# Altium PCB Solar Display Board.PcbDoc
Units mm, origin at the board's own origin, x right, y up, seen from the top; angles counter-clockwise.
Board outline 45 x 20 mm, 2 copper layers (Top Layer, Bottom Layer), stack 1.57 mm thick; 17 components, 18 nets, 42 pads, 3 vias.
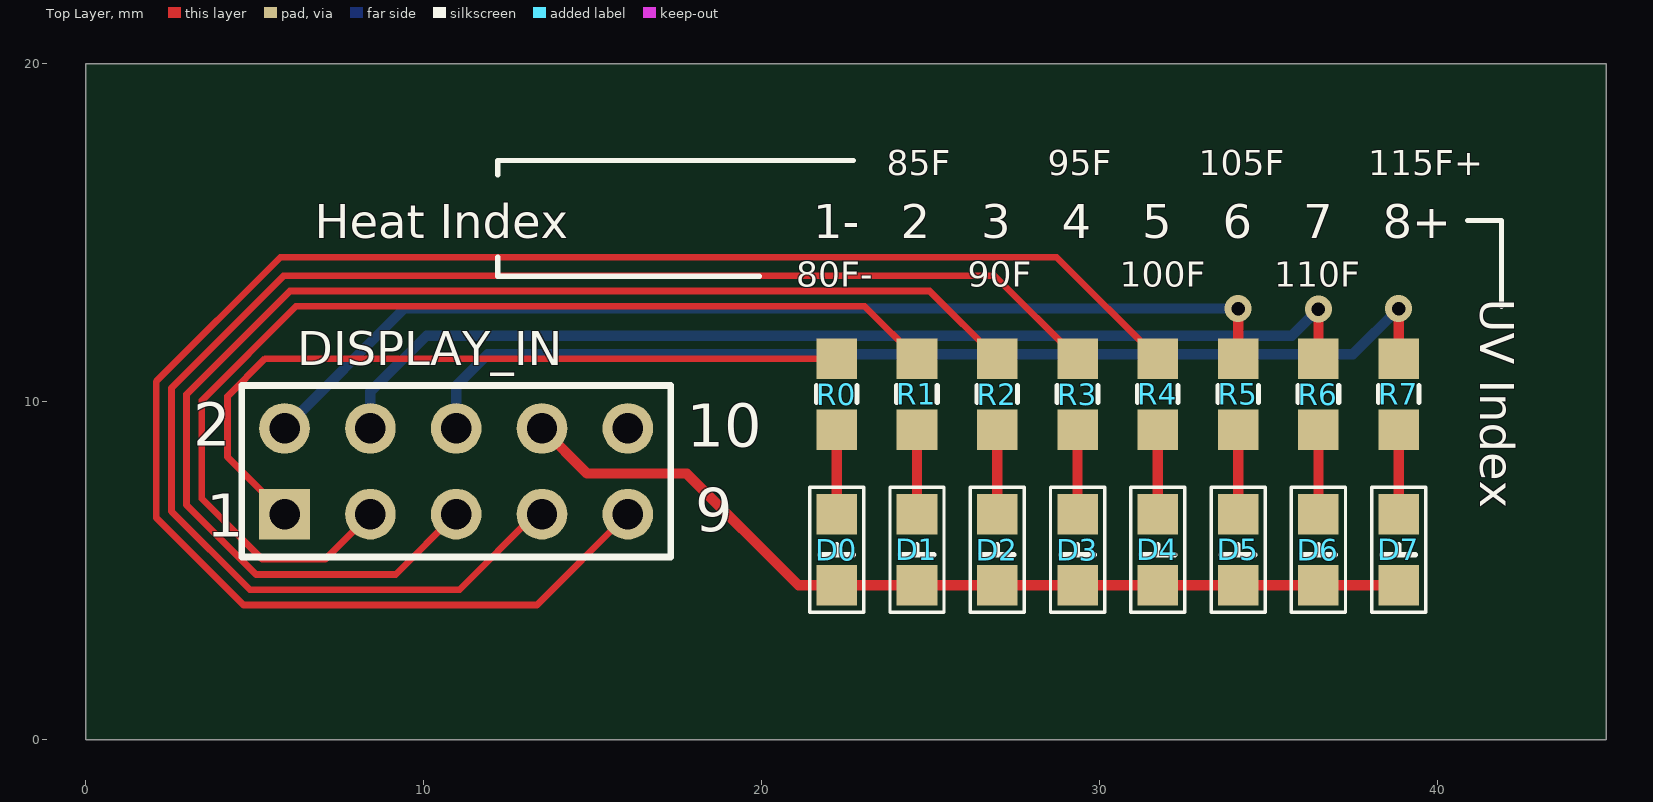
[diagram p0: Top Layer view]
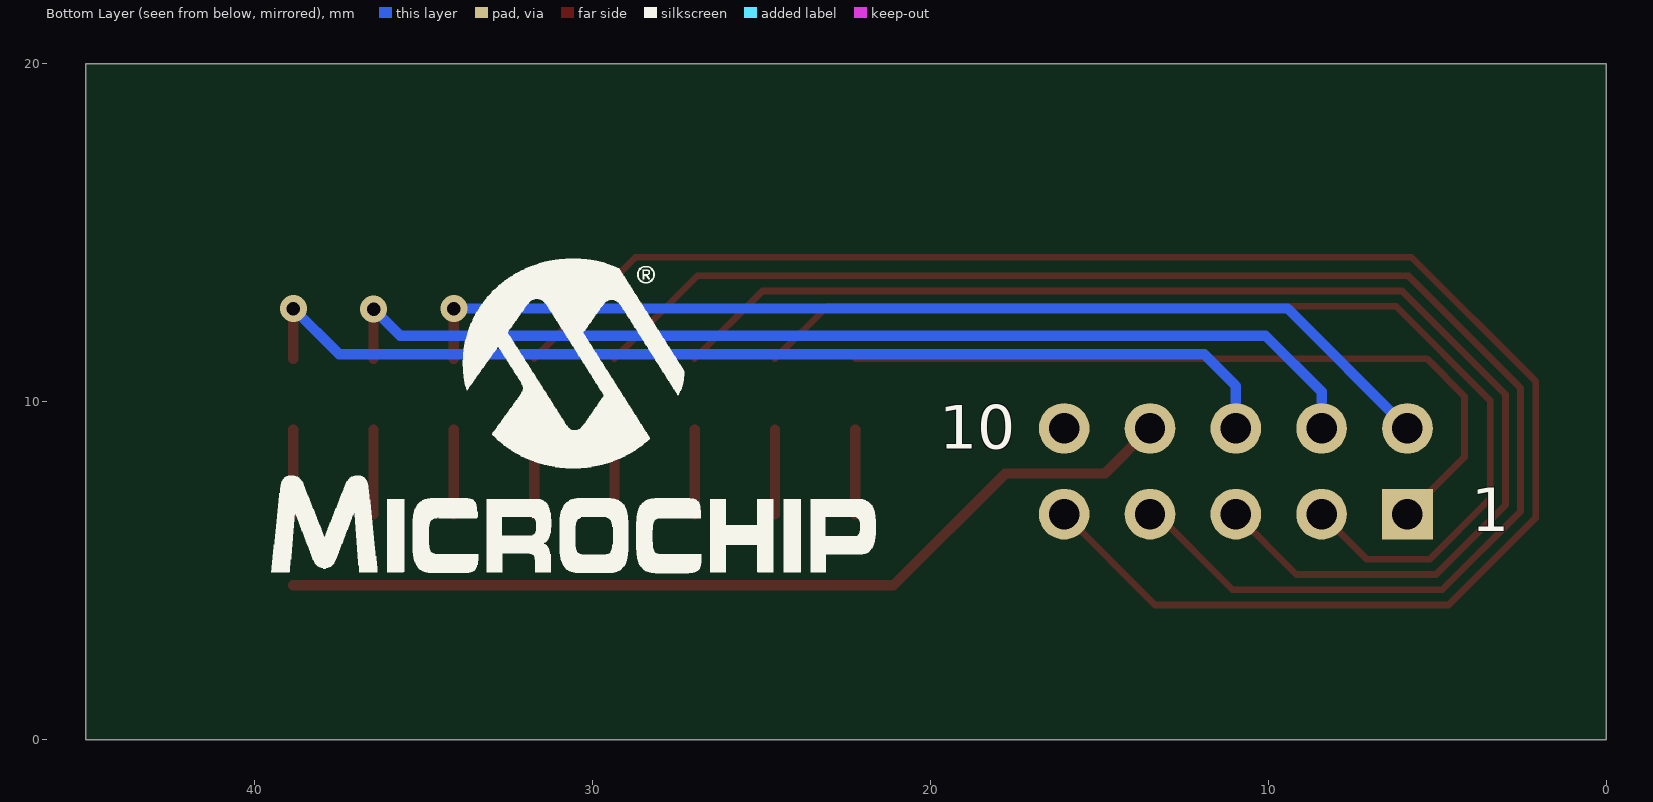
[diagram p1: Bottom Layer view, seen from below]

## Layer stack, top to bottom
Top Solder: solder mask 0.01, Solder Resist, Dk 3.5
Top Layer: signal copper 0.035
Dielectric1: core 1.5, FR-4, Dk 4.8
Bottom Layer: signal copper 0.035
Bottom Solder: solder mask 0.01, Solder Resist, Dk 3.5

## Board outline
0,0 0,20 45,20 45,0

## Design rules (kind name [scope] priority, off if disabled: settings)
AcuteAngle [All] p1: minimum=9.00000000000000E+0001 checktracksonly=TRUE
BoardOutlineClearance BoardOutlineClearance_Overlay [OnLayer('Top Overlay','Bottom Overlay')] p1: gap=0.2 ignorepadtopadclearanceinfootprint=FALSE
BoardOutlineClearance [All] p2: gap=0.5 ignorepadtopadclearanceinfootprint=FALSE
Clearance "Net to Polygon 0.5mm" [InNet('your net here') vs (IsRegion)] p1: gap=0.5 ignorepadtopadclearanceinfootprint=FALSE
Clearance "Poly 0.3mm" [(IsRegion)] p2: gap=0.3 ignorepadtopadclearanceinfootprint=FALSE
Clearance [All] p3: gap=0.25 ignorepadtopadclearanceinfootprint=TRUE
ComponentClearance ComponentClearance_ignore [HasFootprint('NET_TIE_0.5mm')] p1: gap=0 collisioncheckmode=3 verticalgap=0 showdistances=FALSE
ComponentClearance [All] p2: gap=0.2 collisioncheckmode=3 verticalgap=0.2 showdistances=FALSE
DiffPairsRouting [All] p1: maxlimit=0.25 minlimit=0.25 mostfreqgap=0.25 toplayer_minwidth=0.25 toplayer_maxwidth=0.25 toplayer_prefwidth=0.25 bottomlayer_minwidth=0.25 bottomlayer_maxwidth=0.25 bottomlayer_prefwidth=0.25 maxuncoupledlength=12.7
FabricationTestPointUsage TestPointUsage [All] p1: valid=0 allowmultiple=FALSE
FabricationTestpoint Testpoint [All] p1: side=3 testpointundercomponent=TRUE minsize=1.016 maxsize=2.54 preferedsize=1.524 minholesize=0 maxholesize=1.016 preferedholesize=0.813 testpointgrid=0.025 allowsidetop=TRUE allowsidebottom=TRUE usegrid=TRUE gridtolerance=0
HoleSize [All] p1: absolutevalues=TRUE maxlimit=6 minlimit=0.25 maxpercent=80.000 minpercent=20.000
HoleToHoleClearance [All] p1: gap=0.3 allowstackedmicrovias=FALSE
MinimumAnnularRing [All] p1: minimumring=0.15
MinimumSolderMaskSliver [All] p1: minsoldermaskwidth=0.15
PasteMaskExpansion PasteMaskExpansion_DNP [IsPad AND HasCompParameterValue('Populated','DNP')] p1: expansion=-5
PasteMaskExpansion [All] p2: expansion=0
PlaneClearance PlaneClearance_pads [IsPad] p1: clearance=0.3
PlaneClearance PlaneClearance_drill [IsObjectKind('Hole')] p2: clearance=0.4
PlaneConnect PlaneConnect_full [IsVia] p1: planeconnectstyle=Direct reliefexpansion=0.5 reliefentries=4 reliefconductorwidth=0.3 reliefairgap=0.3
PlaneConnect [All] p2: planeconnectstyle=Relief reliefexpansion=0.3 reliefentries=4 reliefconductorwidth=0.25 reliefairgap=0.25
PolygonConnect PolygonConnect_0.7 [IsNamedPolygon('0.7mm') vs (InPadClass('All Pads'))] p1: connectstyle=Relief reliefconductorwidth=0.7 reliefentries=4 polygonreliefangle="90 Angle" airgapwidth=0.25
PolygonConnect PolygonConnect_0.5 [IsNamedPolygon('0.5mm') vs (InPadClass('All Pads'))] p2: connectstyle=Relief reliefconductorwidth=0.5 reliefentries=4 polygonreliefangle="90 Angle" airgapwidth=0.25
PolygonConnect PolygonConnect_full [All vs IsVia or IsNamedPolygon('full')] p3: connectstyle=Direct reliefconductorwidth=0 reliefentries=4 polygonreliefangle="90 Angle" airgapwidth=0.254
PolygonConnect [All] p4: connectstyle=Relief reliefconductorwidth=0.3 reliefentries=4 polygonreliefangle="90 Angle" airgapwidth=0.25
RoutingCorners [All] p1: cornerstyle=45-Degree minsetback=2.5 maxsetback=2.5
RoutingVias [All] p1: holewidth=0.4 width=0.8 viastyle="Through Hole" minholewidth=0.3 minwidth=0.7 maxholewidth=1.6 maxwidth=2.5
SMDToCorner [All] p1: distance=39370
ShortCircuit [IsNet] p1: allowed=FALSE
SilkToSilkClearance [All] p1: silktosilkclearance=0.15
SilkToSolderMaskClearance SilkscreenOverComponentPads [IsPad] p1: minsilkscreentomaskgap=0.2 clearancetoexposedcopper=TRUE
SolderMaskExpansion SolderMaskExpansion_Component_Via [IsComponentVia] p1: expansion=0.075 istentingtop=FALSE soldermaskfromhole=TRUE
SolderMaskExpansion [All] p2: expansion=0.1 istentingtop=FALSE
UnRoutedNet [All] p1: checkbadconnections=TRUE
ViasUnderSMD [All] p1: allowed=FALSE
Width [All] p1: maxlimit=7 minlimit=0.2 preferedwidth=0.25
15 further rules are at their usual default settings.

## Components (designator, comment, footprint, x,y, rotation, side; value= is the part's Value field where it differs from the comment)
D0 "LED" "0805 for LED" 22.225,4.572 r90 top
D1 "LED" "0805 for LED" 24.602,4.572 r90 top
D2 "LED" "0805 for LED" 26.978,4.572 r90 top
D3 "LED" "0805 for LED" 29.355,4.572 r90 top
D4 "LED" "0805 for LED" 31.732,4.572 r90 top
D5 "LED" "0805 for LED" 34.109,4.572 r90 top
D6 "LED" "0805 for LED" 36.485,4.572 r90 top
D7 "LED" "0805 for LED" 38.862,4.572 r90 top
DISPLAY_IN "Header 5X2" HDR2X5 5.88,6.672 r0 top
R0 "Resistor" 0805 22.225,11.275 r270 top value=330
R1 "Resistor" 0805 24.602,11.275 r270 top value=330
R2 "Resistor" 0805 26.978,11.275 r270 top value=330
R3 "Resistor" 0805 29.355,11.275 r270 top value=330
R4 "Resistor" 0805 31.732,11.275 r270 top value=330
R5 "Resistor" 0805 34.109,11.275 r270 top value=330
R6 "Resistor" 0805 36.485,11.275 r270 top value=330
R7 "Resistor" 0805 38.862,11.275 r270 top value=330

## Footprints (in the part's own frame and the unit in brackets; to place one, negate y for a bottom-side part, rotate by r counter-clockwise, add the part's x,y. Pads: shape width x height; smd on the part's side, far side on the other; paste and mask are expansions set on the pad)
0805 [mm] "Non-Polarized"
  rect 1.2x1.2 smd: 1(0,0) 2(2.1,0)
  silkscreen extent 0.8,-0.6 1.3,0.6
"0805 for LED" [mm] "Polarized 0805 Package"
  rect 1.2x1.2 smd: A(0,0) K(2.1,0)
  silkscreen extent -0.8,-0.8 2.9,0.8
HDR2X5 [mm] "Connector; Header; 5x2 Position"
  rect 1.5x1.5 hole 0.9: 1(0,0)
  round 1.5 hole 0.9: 2(0,2.54) 3(2.54,0) 4(2.54,2.54) 5(5.08,0) 6(5.08,2.54) 7(7.62,0) 8(7.62,2.54) 9(10.16,0) 10(10.16,2.54)
  silkscreen extent -1.27,-1.27 11.43,3.81

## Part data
D0 D1 D2: LED Color=Green
D3 D4 D5: LED Color=Yellow
D6 D7: LED Color=Red
DISPLAY_IN: "Header, 5-Pin, Dual row"

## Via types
v1: diameter 0.8, hole 0.4, Top Layer to Bottom Layer, 3 vias

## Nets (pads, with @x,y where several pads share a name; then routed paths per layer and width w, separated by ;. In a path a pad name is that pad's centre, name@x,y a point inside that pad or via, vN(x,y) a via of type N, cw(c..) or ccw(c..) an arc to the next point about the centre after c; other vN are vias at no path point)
GND: DISPLAY_IN.10
IO0: DISPLAY_IN.1 R0.1 | length 22.7
  Top Layer w0.2: DISPLAY_IN.1 4.191,8.361 4.191,10.16 5.306,11.275 R0.1
IO1: DISPLAY_IN.3 R1.1 | length 32.2
  Top Layer w0.2: DISPLAY_IN.3 7.082,5.334 5.223,5.334 3.429,7.128 3.429,10.034 6.222,12.827 23.049,12.827 R1.1
IO2: DISPLAY_IN.5 R2.1 | length 38.9
  Top Layer w0.2: DISPLAY_IN.5 9.172,4.884 5.037,4.884 2.979,6.942 2.979,10.221 6.035,13.277 24.976,13.277 R2.1
IO3: DISPLAY_IN.7 R3.1 | length 45.7
  Top Layer w0.2: DISPLAY_IN.7 13.296,6.672 11.058,4.434 4.85,4.434 2.529,6.755 2.529,10.407 5.849,13.727 26.903,13.727 R3.1
IO4: DISPLAY_IN.9 R4.1 | length 52.6
  Top Layer w0.2: DISPLAY_IN.9 13.352,3.984 4.664,3.984 2.079,6.569 2.079,10.594 5.763,14.277 28.729,14.277 R4.1
IO5: DISPLAY_IN.2 R5.1 | length 31.2
  Top Layer w0.305: R5.1 v1(34.109,12.76)
  Bottom Layer w0.305: DISPLAY_IN.2 9.428,12.76 v1(34.109,12.76)
IO6: DISPLAY_IN.4 R6.1 | length 31.6
  Top Layer w0.305: R6.1 v1(36.485,12.742)
  Bottom Layer w0.305: DISPLAY_IN.4 8.42,10.297 10.081,11.957 35.7,11.957 v1(36.485,12.742)
IO7: DISPLAY_IN.6 R7.1 | length 31.6
  Top Layer w0.305: R7.1 v1(38.862,12.76)
  Bottom Layer w0.305: DISPLAY_IN.6 10.96,10.468 11.894,11.403 37.505,11.403 v1(38.862,12.76)
"LED Anode": D0.A D1.A D2.A D3.A D4.A D5.A D6.A D7.A DISPLAY_IN.8 | length 27.3
  Top Layer w0.305: DISPLAY_IN.8 14.838,7.874 17.791,7.874 21.093,4.572 D0.A D1.A D2.A D3.A D4.A D5.A D6.A D7.A
NetD0_K: D0.K R0.2 | length 2.5
  Top Layer w0.305: D0.K R0.2
NetD1_K: D1.K R1.2 | length 2.5
  Top Layer w0.305: D1.K R1.2
NetD2_K: D2.K R2.2 | length 2.5
  Top Layer w0.305: D2.K R2.2
NetD3_K: D3.K R3.2 | length 2.5
  Top Layer w0.305: D3.K R3.2
NetD4_K: D4.K R4.2 | length 2.5
  Top Layer w0.305: D4.K R4.2
NetD5_K: D5.K R5.2 | length 2.5
  Top Layer w0.305: D5.K R5.2
NetD6_K: D6.K R6.2 | length 2.5
  Top Layer w0.305: D6.K R6.2
NetD7_K: D7.K R7.2 | length 2.5
  Top Layer w0.305: D7.K R7.2

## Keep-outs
Keep-Out Layer:
  text "'.Layer_Name'" at 300.5,-158.75 h1.5

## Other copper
Top Layer:
  text "'.ProjectRevisionART'" at 335.678,-158.572 h1.5
  text "'.Layer_Name'" at 300.5,-158.75 h1.5
Bottom Layer:
  text "04-'.ProjectPCBNumber'-R'.ProjectRevisionART'" at 242,-108.5 h1.2
  text ".ProjectRevisionART" at 335.678,-158.572 h1.5
  text ".ProjectRevisionART" at 335.678,-158.572 h1.5
  text "'.ProjectRevisionART'" at 335.678,-158.572 h1.5
  text "'.Layer_Name'" at 300.5,-158.75 h1.5

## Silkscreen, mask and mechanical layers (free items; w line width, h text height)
Top Overlay:
  region: 289.8,-122.1 289.8,-120.1 291.8,-121.1
  lines w0.152: 12.192,14.277 12.192,13.716 19.939,13.716 ; 12.192,16.71 12.192,17.145 22.725,17.145 ; 40.894,15.367 41.91,15.367 41.91,13.97 41.91,12.827
  text "85F" at 23.7,16.71 h0.75
  text "95F" at 28.467,16.71 h0.75
  text "105F" at 32.942,16.71 h0.75
  text "115F+" at 37.961,16.71 h0.75
  text "Heat Index" at 6.774,14.844 h1
  text "1-" at 21.536,14.844 h1
  text "2" at 24.127,14.844 h1
  text "3" at 26.509,14.844 h1
  text "4" at 28.891,14.844 h1
  text "5" at 31.273,14.844 h1
  text "6" at 33.654,14.844 h1
  text "7" at 36.036,14.844 h1
  text "8+" at 38.383,14.844 h1
  text "80F-" at 21.028,13.408 h0.75
  text "90F" at 26.108,13.408 h0.75
  text "100F" at 30.611,13.408 h0.75
  text "110F" at 35.175,13.408 h0.75
  text "UV Index" at 41.275,13.047 h1 r270
  text "C" at 251.245,-112.043 h8
  text "1" at 260.096,-112.649 h5
  text "'.ProjectPartNumber'" at 231.5,-113 h1.2
  text "" at 244.245,-113.346 h8
  text "5" at 278.5,-114.194 h8
  text "7" at 288.5,-114.194 h8
  text "0" at 298.5,-114.194 h8
  text "1" at 308.5,-114.194 h8
  text "6" at 268.5,-114.227 h8
  text "2" at 318.5,-114.227 h8
  text "3" at 328.5,-114.227 h8
  text "4" at 338.58,-114.227 h8
  text "ICD" at 284.4,-122 h1.52
  text "M" at 262,-128.5 h10
  text "" at 315,-128.959 h10
  text "" at 294,-128.984 h10
  text "" at 305,-128.984 h10
  text "" at 324,-128.984 h10
  text "" at 335,-128.984 h10
  text "" at 346,-129.159 h10
  text "*h" at 227.7,-130 h7
  text "" at 286,-132 h10
  text "dsPICDEM.net™" at 185.75,-138.75 h3
  text "mTouch®" at 208,-138.75 h3
  text "chipKIT™" at 222.25,-138.75 h3
  text "dsPICDEM™" at 185.5,-144.5 h3
  text "MPLAB®" at 208,-145 h3
  text "dsPIC®" at 222.25,-145 h3
  text "PICDEM.net™" at 185.5,-150.75 h3
  text "PICkit™" at 208.25,-151 h3
  text "PIC®" at 222.25,-151 h3
  text "PICDEM™" at 185.5,-157.25 h3
  text "PICtail™" at 208.25,-157.25 h3
  text "'.ProjectRevisionART'" at 335.678,-158.572 h1.5
  text "'.Layer_Name'" at 300.5,-158.75 h1.5
Bottom Overlay:
  drawing of 12 lines, arcs and shapes, not listed
  text "10" at 19.739,8.606 h1.3
  text "1" at 3.991,6.169 h1.3
  text "'.ProjectRevisionART'" at 335.678,-158.572 h1.5
  text "'.Layer_Name'" at 300.5,-158.75 h1.5
Top Paste:
  text "'.ProjectRevisionART'" at 335.678,-158.572 h1.5
  text "'.Layer_Name'" at 300.5,-158.75 h1.5
Bottom Paste:
  text "'.ProjectRevisionART'" at 335.678,-158.572 h1.5
  text "'.Layer_Name'" at 300.5,-158.75 h1.5
Top Solder:
  text "'.ProjectRevisionART'" at 335.678,-158.572 h1.5
  text "'.Layer_Name'" at 300.5,-158.75 h1.5
Bottom Solder:
  text "'.ProjectRevisionART'" at 335.678,-158.572 h1.5
  text "'.Layer_Name'" at 300.5,-158.75 h1.5
NOTES (M1):
  text "ASSEMBLY NOTES:" at 29.4,-109.1 h4
  text "1. ALL COMPONENTS SHALL BE RoHS COMPLIANT." at -4.7,-114.2 h3
  text "2. ALL UNUSED THROUGH HOLE COMPONENT LOCATIONS SHALL BE FREE OF SOLDER." at -4.7,-117.2 h3
  text "3. ALL COMPONENTS SHALL BE MOUNTED FLUSH TO THE BOARD, EXCEPT AS NOTED." at -4.7,-120.2 h3
  text "4. FINISHED BOARD SHALL BE FREE OF ALL RESIDUES." at -4.7,-123.2 h3
  text "5. ALL LEADS SHALL BE TRIMMED TO A MAXIMUM HEIGHT OF 2mm" at -4.7,-126.2 h3
  text "'.Layer_Name'" at 318.5,-158.75 h1.5
BOARD (M2):
  the board outline again, w0.1
  text "'.ProjectRevisionART'" at 335.678,-158.572 h1.5
  text "'.Layer_Name'" at 300.5,-158.75 h1.5
REF POINTS (M3):
  text "'.Layer_Name'" at 300.5,-158.75 h1.5
FAB (M4):
  drawing of 284 lines, arcs and shapes, not listed
  text "THIS PCB TO BE MANUFACTURED TO MEET ALL ACCEPTANCE LEVELS" at 236.989,51.662 h1.78
  text "OF A CLASS 2 PCB PER ANSI/IPC-A-600G." at 236.989,47.852 h1.78
  text "MATERIAL:" at 236.989,43.232 h1.78
  text "FR-4 or Equivalent" at 257.309,43.232 h1.78
  text "CONTROLLED IMPEDANCE" at 313.5,39 h1.78
  text "MULTILAYER" at 263.024,38.882 h1.78
  text "2" at 286.519,38.882 h1.78
  text "LAYERS" at 290.964,38.882 h1.78
  text "Cu WEIGHT EXTERNAL LAYERS" at 257.309,34.032 h1.78
  text "35um" at 309.379,34.032 h1.78
  text "FINISHED" at 318.904,34.032 h1.78
  text "Cu WEIGHT INTERNAL LAYERS" at 257.309,29.182 h1.78
  text "N/A" at 309.379,29.182 h1.78
  text "FINISHED" at 318.904,29.182 h1.78
  text "FINISHED OVERALL THICKNESS" at 257.309,24.332 h1.78
  text "1.6" at 310.649,24.332 h1.78
  text "mm" at 318.904,24.332 h1.78
  text "10" at 333.509,24.332 h1.78
  text "%" at 341.764,24.332 h1.78
  text "COPPER THIEVING ALLOWED" at 257.5,19.5 h1.78
  text "YES" at 314.5,19.5 h1.78
  text "NO" at 331.5,19.5 h1.78
  text "X" at 326.091,19 h2.6
  text "FINISH:" at 237,15 h1.78
  text "LEAD-FREE HOT AIR LEVELING" at 263,14.7 h1.78
  text "X" at 258.4,14 h2.6
  text "IMMERSION GOLD" at 263.024,9.162 h1.78
  text "IMMERSION TIN" at 263.024,3.662 h1.78
  text "SMOBC WITH SELECTIVE GOLD PLATING ON LANDS" at 263.024,-0.043 h1.78
  text "INDICATED. 1um GOLD OVER 5-10 um NICKEL" at 263.024,-3.853 h1.78
  text "SOLDERMASK" at 257.309,-9.188 h1.78
  text "DYNACHEM EPIC 200 LPI OR EQUIVALENT" at 278.899,-9.188 h1.78
  text "SOLDERMASK COLOR" at 257.309,-15.538 h1.78
  text "GREEN HIGH GLOSS" at 289.059,-15.538 h1.78
  text "SILKSCREEN COLOR" at 257.309,-21.888 h1.78
  text "WHITE" at 289.059,-21.888 h1.78
  text "Blind / Burried Vias" at 263.5,-28 h1.78
  text "DRILLING:" at 237.5,-28.25 h1.78
  text "Via Layer Pairs" at 258,-32.75 h1.78
  text "Top-Bottom" at 278.75,-32.75 h1.78
  text "ALL HOLES TO BE LOCATED BY THE COORDINATES FROM THE NC DRILL DATA PROVIDED." at 236.989,-38 h1.78
  text "05-'.ProjectPCBNumber'" at 269,-44.5 h1.78
  text "PCB REV" at 305,-44.5 h1.78
  text "USE ARTWORK SET NO." at 236.989,-44.588 h1.78
  text "'.ProjectRevisionART'" at 318.15,-44.75 h1.78
  text "ALL UL LOGO, MANUFACTURER'S ID, AND DATE CODES SHALL BE PLACED" at 236.989,-50.938 h1.78
  text "ON THE BOTTOM SIDE UNLESS OTHERWISE INDICATED." at 236.989,-54.748 h1.78
  text "ANY ALTERNATIVES TO THE ABOVE SPECIFICATIONS MUST FIRST BE APPROVED." at 236.5,-60 h1.78
  text "Layer" at 224.029,-66.675 h1.52
  text "Name" at 234.441,-66.675 h1.52
  text "Material" at 258.056,-66.675 h1.52
  text "Thickness" at 279.894,-66.675 h1.52
  text "Constant" at 296.4,-66.675 h1.52
  text "Gerber" at 310.875,-66.675 h1.52
  text "Board Layer Stack" at 322.81,-66.675 h1.52
  text "Top Overlay" at 234.441,-69.723 h1.52
  text "GTO" at 310.875,-69.723 h1.52
  text "Top Solder" at 234.441,-72.771 h1.52
  text "Solder Resist" at 258.056,-72.771 h1.52
  text "0.010mm" at 279.894,-72.771 h1.52
  text "3.5" at 296.4,-72.771 h1.52
  text "GTS" at 310.875,-72.771 h1.52
  text "1" at 224.029,-75.819 h1.52
  text "Top Layer" at 234.441,-75.819 h1.52
  text "0.035mm" at 279.894,-75.819 h1.52
  text "GTL" at 310.875,-75.819 h1.52
  text "Dielectric1" at 234.441,-78.867 h1.52
  text "FR-4" at 258.056,-78.867 h1.52
  text "1.500mm" at 279.894,-78.867 h1.52
  text "4.8" at 296.4,-78.867 h1.52
  text "2" at 224.029,-81.915 h1.52
  text "Bottom Layer" at 234.441,-81.915 h1.52
  text "0.035mm" at 279.894,-81.915 h1.52
  text "GBL" at 310.875,-81.915 h1.52
  text "Bottom Solder" at 234.441,-84.963 h1.52
  text "Solder Resist" at 258.056,-84.963 h1.52
  text "0.010mm" at 279.894,-84.963 h1.52
  text "3.5" at 296.4,-84.963 h1.52
  text "GBS" at 310.875,-84.963 h1.52
  text "Bottom Overlay" at 234.441,-88.011 h1.52
  text "GBO" at 310.875,-88.011 h1.52
  text "Total board thickness:" at 224.029,-91.059 h1.52
  text "1.590mm" at 279.894,-91.059 h1.52
  text "'.ProjectRevisionFAB'" at 335.678,-158.572 h1.5
  text "'.Layer_Name'" at 300.5,-158.75 h1.5
Case (M5):
  text "'.Layer_Name'" at 300.5,-158.75 h1.5
Cover (M6):
  text "'.Layer_Name'" at 300.5,-158.75 h1.5
Terminal Block (M7):
  text "'.Layer_Name'" at 300.5,-158.75 h1.5
Route Tool Path:
  text "'.Layer_Name'" at 300.5,-158.75 h1.5
V-Cut (M9):
  text "'.Layer_Name'" at 300.5,-158.75 h1.5
Bottom Assembly:
  text "'.VariantName'" at 50.07,-142.75 h0.9
  text "ASSEMBLY VARIANT:" at 64.32,-142.75 h0.9
  text "DOCUMENT NUMBER:" at 18.05,-151 h1.14
  text "02-'.ProjectPCBAssyNumber'-D" at 17.8,-154 h1.6
  text "'.ProjectRevisionASSY'" at 1.122,-158.572 h1.5
  text "'.Layer_Name'" at 36,-158.75 h1
Top Assembly:
  text "6. PLACE LABEL  ON THE LOCATION INDICATED." at -4.7,-129.2 h3
  text "7." at -4.7,-132.2 h3
  text "ASSEMBLY VARIANT:" at 272.5,-142.75 h0.9
  text "'.VariantName'" at 286.75,-142.75 h0.9
  text "DOCUMENT NUMBER:" at 318.75,-151 h1.15
  text "02-'.ProjectPCBAssyNumber'-D" at 319,-154 h1.6
  text "'.ProjectRevisionASSY'" at 335.678,-158.572 h1.5
  text "'.Layer_Name'" at 300.5,-158.75 h1
Bottom 3D Body:
  text "'.Layer_Name'" at 300.5,-158.75 h1.15
Top 3D Body:
  text "'.Layer_Name'" at 300.5,-158.75 h1.2
Bottom Courtyard:
  text ".ProjectRevisionART" at 335.678,-158.572 h1.5
  text "'.Layer_Name'" at 300.5,-158.75 h1
Top Courtyard:
  text "'.ProjectRevisionART'" at 335.678,-158.572 h1.5
  text "'.Layer_Name'" at 300.5,-158.75 h1.1
TITLE (M16):
  lines w0.1: 272,-141.5 353.82,-141.5 ; 324,-134 324,-137 353.82,-137 ; 342.54,-158.635 342.54,-157.365 ; 342.54,-158 352.7,-158 ; 342.7,-156.8 342.7,-155.8 ; 342.7,-156.3 352.7,-156.3 ; 345.08,-158.635 345.08,-157.365 ; 347.62,-158.635 347.62,-157.365 ; 347.7,-156.6 347.7,-156 ; 350.16,-158.635 350.16,-157.365 ; 352.7,-158.635 352.7,-157.365 ; 352.7,-156.8 352.7,-155.8 ; 353.82,-137 353.82,-137
  lines w0.127: -22.1,-104.175 -17.02,-104.175 ; -22.1,-43.85 -17.02,-43.85 ; -22.1,16.475 -17.02,16.475 ; 41.4,-164.5 41.4,-159.42 ; 41.4,71.72 41.4,76.8 ; 104.9,-164.5 104.9,-159.42 ; 104.9,71.72 104.9,76.8 ; 168.4,-164.5 168.4,-159.42 ; 168.4,71.72 168.4,76.8 ; 203.96,-159.42 239.52,-159.42 ; 231.9,-164.5 231.9,-159.42 ; 231.9,71.72 231.9,76.8 ; 272,-159.42 272,-134 ; 272,-155 353.82,-155 ; 272,-149 353.82,-149 ; 272,-143 353.82,-143 ; 295.4,-164.5 295.4,-159.42 ; 295.4,71.72 295.4,76.8 ; 300,-159.42 300,-143 ; 318,-155 318,-149 ; 331,-159.42 331,-155 ; 338.5,-159.42 338.5,-149 ; 353.82,-128.94 353.82,-159.42 ; 353.82,-104.175 358.9,-104.175 ; 353.82,-43.85 358.9,-43.85 ; 353.82,16.475 358.9,16.475 ; 353.82,-159.42 353.82,-134 238,-134 238,-159.42 353.82,-159.42 ; 353.82,-159.42 -17.02,-159.42 -17.02,71.72 353.82,71.72 353.82,-159.42 ; -22.1,-164.5 358.9,-164.5 358.9,76.8 -22.1,76.8 -22.1,-164.5
  lines w0.254: 243.32,62.72 243.32,67.22 243.32,71.72 ; 255.82,62.72 255.82,67.22 255.82,71.72 ; 334.32,62.72 334.32,67.22 334.32,71.72 ; 353.82,67.22 232.32,67.22 ; 232.32,67.22 232.32,71.72 353.82,71.72 353.82,62.72 232.32,62.72 232.32,67.22
  text "1" at 9.176,73.498 h1.78
  text "2" at 72.566,73.498 h1.78
  text "3" at 135.795,73.498 h1.78
  text "4" at 199.464,73.498 h1.78
  text "5" at 262.939,73.498 h1.78
  text "6" at 326.566,73.498 h1.78
  text "REV" at 234.82,68.72 h1.52
  text "ECO" at 244.82,68.72 h1.52
  text "Comments" at 291.32,68.22 h1.52
  text "Date" at 339.32,68.22 h1.52
  text "A" at -20.195,44.466 h1.78
  text "A" at 355.725,44.466 h1.78
  text "B" at -20.195,-15.986 h1.78
  text "B" at 355.725,-15.986 h1.78
  text "C" at -20.195,-76.311 h1.78
  text "C" at 355.725,-76.311 h1.78
  text "PART NUMBER:" at 325,-136 h1
  text "'.ProjectpartNumber'" at 337,-136.25 h1.5
  text "D" at -20.195,-136.509 h1.78
  text "TITLE:" at 273,-136.5 h1.14
  text "D" at 355.725,-136.509 h1.78
  text "'.ProjectTitle'" at 273,-140.5 h2.5
  text "PCB Layout Contact:" at 273,-145 h1.15
  text "GERBER FILE:" at 301,-145 h1.15
  text "'.ProjectDrawnBy'" at 273,-148 h1.6
  text "'.Plot_File_Name'" at 301,-148 h1.5
  text "M" at 241,-150 h15.24
  text "Project Owner:" at 273,-151 h1.15
  text "BOARD NUMBER:" at 301,-151 h1.15
  text "DATE:" at 339.7,-151 h1.14
  text "Microchip Technology Inc." at 239.77,-153.26 h1.78
  text "'.ProjectEngineer'" at 273,-154 h1.6
  text "04-'.ProjectPCBNumber'" at 301,-154 h1.6
  text "'.PRINT_DATE'" at 339.7,-154 h1.5
  text "2355 W. Chandler Blvd." at 241,-156 h1.78
  text "LAYER NAME:" at 301,-156.5 h1.14
  text "10mm" at 339,-156.6 h0.7
  text "PCB FILE NAME:" at 273,-156.75 h1.15
  text "REV:" at 331.75,-156.75 h1.14
  text "400mil" at 338.9,-158.3 h0.7
  text "Chandler, AZ  85224" at 242,-158.5 h1.78
  text "'.PCB_FILE_NAME_NO_PATH'" at 273,-158.75 h1
  text "1" at 9.176,-162.722 h1.78
  text "2" at 72.566,-162.722 h1.78
  text "3" at 135.795,-162.722 h1.78
  text "4" at 199.464,-162.722 h1.78
  text "5" at 262.939,-162.722 h1.78
  text "6" at 326.566,-162.722 h1.78
Drill Drawing:
  circle w0.25: c-5.348,-78.845 r0.833
  lines w0.25: -6.181,-83.429 -4.514,-83.429 -4.514,-81.762 -6.181,-81.762 -6.181,-83.429
  lines w0.3: -7.676,-84.554 197.117,-84.554 ; -7.676,-77.054 197.117,-77.054 ; 6.096,-88.304 6.096,-73.304 ; 23.541,-88.304 23.541,-73.304 ; 57.182,-88.304 57.182,-73.304 ; 69.828,-88.304 69.828,-73.304 ; 107.317,-88.304 107.317,-73.304 ; 122.063,-88.304 122.063,-73.304 ; 140.408,-88.304 140.408,-73.304 ; 162.052,-88.304 162.052,-73.304 ; -7.676,-88.304 197.117,-88.304 197.117,-73.304 -7.676,-73.304 -7.676,-88.304
  text "Symbol" at -5.426,-75.929 h1.8
  text "Hit Count" at 7.221,-75.929 h1.8
  text "Finished Hole Size" at 24.666,-75.929 h1.8
  text "Plated" at 58.307,-75.929 h1.8
  text "Drill Layer Pair" at 70.953,-75.929 h1.8
  text "Via/Pad" at 108.442,-75.929 h1.8
  text "Hole Type" at 123.188,-75.929 h1.8
  text "Hole Length" at 141.533,-75.929 h1.8
  text "Routed Path Length" at 163.177,-75.929 h1.8
  text "3" at 7.221,-79.679 h1.5
  text "0.400mm (15.75mil)" at 24.666,-79.679 h1.5
  text "PTH" at 58.307,-79.679 h1.5
  text "Top Layer - Bottom Layer" at 70.953,-79.679 h1.5
  text "Via" at 108.442,-79.679 h1.5
  text "Round" at 123.188,-79.679 h1.5
  text "-" at 141.533,-79.679 h1.5
  text "-" at 163.177,-79.679 h1.5
  text "10" at 7.221,-83.429 h1.5
  text "0.900mm (35.43mil)" at 24.666,-83.429 h1.5
  text "PTH" at 58.307,-83.429 h1.5
  text "Top Layer - Bottom Layer" at 70.953,-83.429 h1.5
  text "Pad" at 108.442,-83.429 h1.5
  text "Round" at 123.188,-83.429 h1.5
  text "-" at 141.533,-83.429 h1.5
  text "-" at 163.177,-83.429 h1.5
  text "13 Total" at 7.221,-87.179 h1.5
  text "DOCUMENT NUMBER:" at 318.75,-151 h1.15
  text "04-'.ProjectPCBNumber'-D" at 319,-154 h1.6
  text "'.ProjectRevisionFAB'" at 335.678,-158.572 h1.5
TITLE MIRROR (M17):
  lines w0.1: -15.9,-158.635 -15.9,-157.365 ; -15.9,-158 -5.74,-158 ; -15.9,-156.8 -15.9,-155.8 ; -15.9,-156.3 -5.9,-156.3 ; -13.36,-158.635 -13.36,-157.365 ; -10.9,-156.6 -10.9,-156 ; -10.82,-158.635 -10.82,-157.365 ; -8.28,-158.635 -8.28,-157.365 ; -5.9,-156.8 -5.9,-155.8 ; -5.74,-158.635 -5.74,-157.365
  lines w0.127: -22.1,-104.175 -17.02,-104.175 ; -22.1,-43.85 -17.02,-43.85 ; -22.1,16.475 -17.02,16.475 ; -17.02,-155 64.8,-155 ; -17.02,-149 64.8,-149 ; -17,-143 64.82,-143 ; -17,-141.5 64.82,-141.5 ; -17,-137 -16.383,-137 ; -1.7,-159.42 -1.7,-149 ; 5.8,-159.42 5.8,-155 ; 12.82,-134 12.82,-137 -16.383,-137 ; 18.8,-155 18.8,-149 ; 36.82,-159.42 36.82,-143 ; 41.4,-164.5 41.4,-159.42 ; 41.4,71.72 41.4,76.8 ; 64.82,-159.42 64.82,-134 ; 104.9,-164.5 104.9,-159.42 ; 104.9,71.72 104.9,76.8 ; 168.4,-164.5 168.4,-159.42 ; 168.4,71.72 168.4,76.8 ; 231.9,-164.5 231.9,-159.42 ; 231.9,71.72 231.9,76.8 ; 295.4,-164.5 295.4,-159.42 ; 295.4,71.72 295.4,76.8 ; 353.82,-104.175 358.9,-104.175 ; 353.82,-43.85 358.9,-43.85 ; 353.82,16.475 358.9,16.475 ; -17.02,-159.42 98.82,-159.42 98.82,-134 -17.02,-134 -17.02,-159.42 ; -17.02,-159.42 -17.02,71.72 353.82,71.72 353.82,-159.42 -17.02,-159.42 ; -16.383,-137 -16.383,-137 ; -22.1,-164.5 -22.1,76.8 358.9,76.8 358.9,-164.5 -22.1,-164.5
  text "6" at 10.234,73.498 h1.78
  text "5" at 73.861,73.498 h1.78
  text "4" at 137.336,73.498 h1.78
  text "3" at 201.005,73.498 h1.78
  text "2" at 264.234,73.498 h1.78
  text "1" at 327.624,73.498 h1.78
  text "A" at -18.925,44.466 h1.78
  text "A" at 356.995,44.466 h1.78
  text "B" at -18.925,-15.986 h1.78
  text "B" at 356.995,-15.986 h1.78
  text "C" at -18.925,-76.311 h1.78
  text "C" at 356.995,-76.311 h1.78
  text "PART NUMBER:" at 11.82,-136 h1
  text "TITLE:" at 63.82,-136 h1.14
  text "'.ProjectpartNumber'" at -0.18,-136.25 h1.5
  text "D" at -18.925,-136.509 h1.78
  text "D" at 356.995,-136.509 h1.78
  text "'.ProjectTitle'" at 63.82,-140.5 h2.5
  text "GERBER FILE:" at 35.82,-145 h1.14
  text "PCB DESIGNER:" at 63.82,-145 h1.14
  text "'.Plot_File_Name'" at 35.82,-148 h1.5
  text "'.ProjectDrawnBy'" at 63.82,-148 h1.78
  text "M" at 95.82,-150 h15.24
  text "DATE:" at -2.9,-151 h1.14
  text "BOARD NUMBER:" at 35.8,-151 h1.14
  text "ENGINEER:" at 63.8,-151 h1.14
  text "Microchip Technology Inc." at 97.05,-153.26 h1.78
  text "'.PRINT_DATE'" at -2.9,-154 h1.5
  text "04-'.ProjectPCBNumber'" at 35.8,-154 h1.6
  text "'.ProjectEngineer'" at 63.8,-154 h1.78
  text "2355 W. Chandler Blvd." at 95.82,-156 h1.78
  text "LAYER NAME:" at 35.8,-156.5 h1.14
  text "10mm" at -2.2,-156.6 h0.7
  text "REV:" at 5.05,-156.75 h1.14
  text "PCB FILE NAME:" at 63.8,-156.75 h1.14
  text "400mil" at -2.1,-158.3 h0.7
  text "Chandler, AZ  85224" at 94.82,-158.5 h1.78
  text "'.PCB_FILE_NAME_NO_PATH'" at 63.8,-158.75 h1.14
  text "6" at 10.234,-162.722 h1.78
  text "5" at 73.861,-162.722 h1.78
  text "4" at 137.336,-162.722 h1.78
  text "3" at 201.005,-162.722 h1.78
  text "2" at 264.234,-162.722 h1.78
  text "1" at 327.624,-162.722 h1.78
